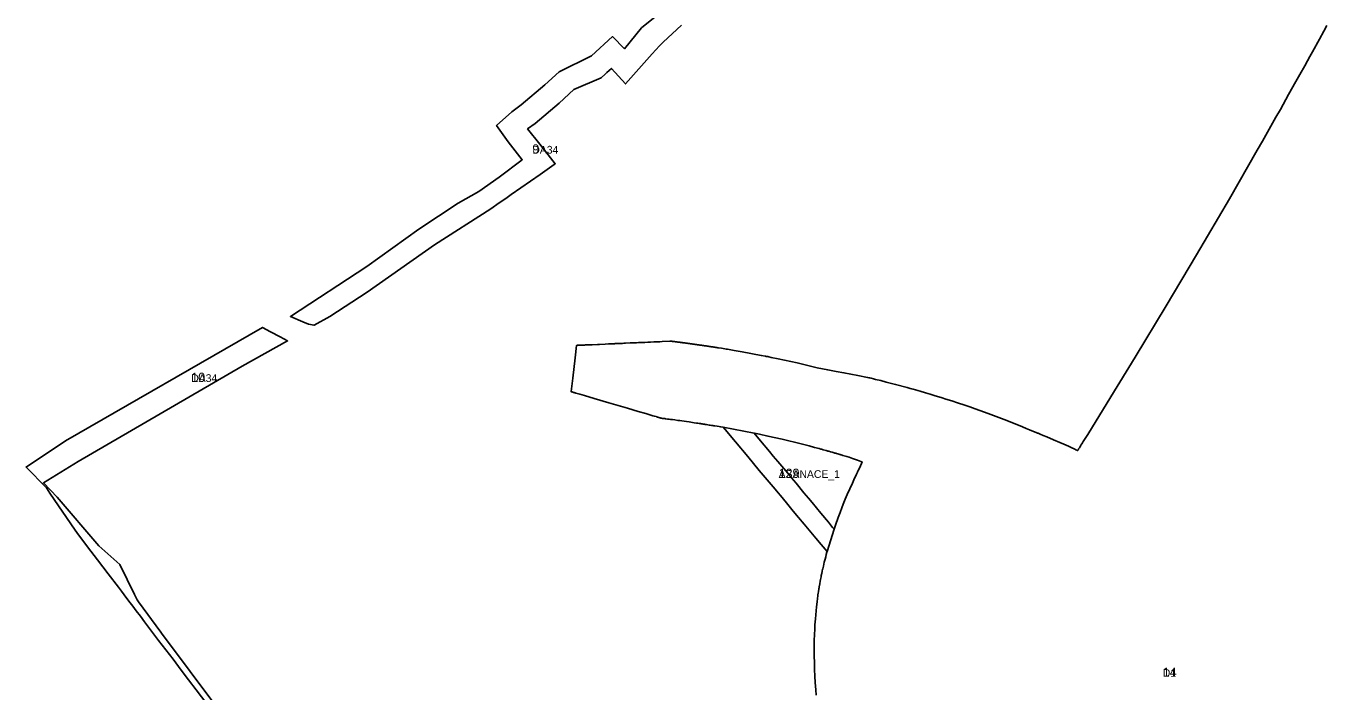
# Model space of a CAD drawing. Extents: x -537012 to -534603, y -1176562 to -1172739.
# Drawn here: x -536960 to -536122, y -1174561 to -1174132 of the extents above; entities that cross this region are included whole.
import ezdxf

# ---------------------------------------------------------------- set-up
doc = ezdxf.new("R2010")
doc.units = 0
for name, color, linetype in [('96070023', 7, 'Continuous'), ('96120023', 7, 'Continuous'), ('96140023', 7, 'Continuous'), ('ID_A', 7, 'Continuous'), ('ID_VPO', 7, 'Continuous'), ('ID_VPS', 7, 'Continuous')]:
    doc.layers.add(name, color=color, linetype=linetype)

msp = doc.modelspace()

# ---------------------------------------------------------------- linework, layer by layer
at = {"layer": '96070023'}
msp.add_lwpolyline([(-536510.97, -1174390.13), (-536491.16, -1174393.88), (-536487.08, -1174398.75), (-536481.33, -1174405.62), (-536478.81, -1174408.63), (-536475.89, -1174412.11), (-536469.54, -1174419.69), (-536467.05, -1174422.67), (-536464.18, -1174426.13), (-536459.11, -1174432.25), (-536456.15, -1174435.81), (-536453.87, -1174438.55), (-536448.28, -1174445.29), (-536443.37, -1174451.21), (-536440.62, -1174454.52), (-536439.72, -1174455.61), (-536444.22, -1174470.15), (-536448.09, -1174465.49), (-536451.43, -1174461.48), (-536458.89, -1174452.51), (-536462.53, -1174448.14), (-536465.96, -1174444.02), (-536469.4, -1174439.87), (-536473.17, -1174435.33), (-536476.74, -1174431.03), (-536477.7, -1174429.89), (-536481.51, -1174425.34), (-536487.81, -1174417.82), (-536495.28, -1174408.89), (-536503.16, -1174399.47), (-536509.84, -1174391.48)], close=True, dxfattribs=at)
at = {"layer": '96120023'}
msp.add_lwpolyline([(-536451.2, -1174562.49), (-536451.47, -1174559.05), (-536451.8, -1174554.37), (-536452.04, -1174550.3), (-536452.23, -1174546.1), (-536452.35, -1174542.66), (-536452.48, -1174536.44), (-536452.5, -1174532.78), (-536452.43, -1174527.15), (-536452.33, -1174523.79), (-536452.16, -1174519.88), (-536452.02, -1174517.4), (-536451.75, -1174513.36), (-536451.53, -1174510.81), (-536451.29, -1174508.22), (-536451.02, -1174505.61), (-536450.65, -1174502.44), (-536450.38, -1174500.38), (-536450.16, -1174498.73), (-536450.06, -1174498.03), (-536449.9, -1174496.98), (-536449.75, -1174495.96), (-536449.63, -1174495.19), (-536449.58, -1174494.88), (-536449.54, -1174494.59), (-536449.48, -1174494.26), (-536449.44, -1174493.97), (-536449.4, -1174493.77), (-536449.38, -1174493.66), (-536449.37, -1174493.59), (-536449.36, -1174493.51), (-536449.35, -1174493.46), (-536449.35, -1174493.45), (-536449.34, -1174493.41), (-536449.34, -1174493.4), (-536449.34, -1174493.39), (-536449.34, -1174493.38), (-536449.34, -1174493.37), (-536449.33, -1174493.36), (-536449.33, -1174493.35), (-536449.33, -1174493.34), (-536449.32, -1174493.29), (-536449.32, -1174493.28), (-536449.32, -1174493.25), (-536449.31, -1174493.22), (-536449.3, -1174493.17), (-536449.3, -1174493.16), (-536449.3, -1174493.15), (-536449.3, -1174493.13), (-536449.29, -1174493.12), (-536449.29, -1174493.11), (-536449.29, -1174493.1), (-536449.29, -1174493.09), (-536449.29, -1174493.07), (-536449.28, -1174493.06), (-536449.27, -1174492.95), (-536449.26, -1174492.94), (-536449.26, -1174492.93), (-536449.26, -1174492.91), (-536449.25, -1174492.87), (-536449.25, -1174492.83), (-536448.92, -1174490.92), (-536448.6, -1174489.21), (-536448.4, -1174488.1), (-536448.06, -1174486.4), (-536447.9, -1174485.53), (-536447.78, -1174484.97), (-536447.76, -1174484.86), (-536447.74, -1174484.78), (-536447.74, -1174484.77), (-536447.73, -1174484.75), (-536447.73, -1174484.74), (-536447.73, -1174484.73), (-536447.72, -1174484.7), (-536447.71, -1174484.65), (-536447.7, -1174484.59), (-536447.68, -1174484.5), (-536447.66, -1174484.39), (-536447.65, -1174484.33), (-536447.63, -1174484.24), (-536447.62, -1174484.19), (-536447.6, -1174484.11), (-536447.59, -1174484.05), (-536447.57, -1174483.97), (-536447.56, -1174483.92), (-536447.54, -1174483.83), (-536447.53, -1174483.76), (-536447.5, -1174483.64), (-536447.48, -1174483.54), (-536447.44, -1174483.34), (-536447.27, -1174482.55), (-536447.06, -1174481.6), (-536446.96, -1174481.14), (-536446.6, -1174479.57), (-536445.99, -1174476.98), (-536445.48, -1174474.94), (-536445.09, -1174473.42), (-536444.7, -1174471.91), (-536444.29, -1174470.42), (-536444.22, -1174470.15), (-536439.72, -1174455.61), (-536438.86, -1174453.07), (-536437.13, -1174448.29), (-536435.86, -1174444.91), (-536434.73, -1174442.03), (-536433.76, -1174439.61), (-536432.46, -1174436.46), (-536431.16, -1174433.39), (-536429.52, -1174429.63), (-536427.91, -1174426.04), (-536426.96, -1174423.95), (-536425.23, -1174420.22), (-536425.08, -1174419.89), (-536424.92, -1174419.56), (-536424.77, -1174419.23), (-536424.61, -1174418.91), (-536424.3, -1174418.25), (-536424.15, -1174417.93), (-536423.84, -1174417.28), (-536423.54, -1174416.64), (-536423.39, -1174416.33), (-536423.08, -1174415.69), (-536422.78, -1174415.06), (-536422.63, -1174414.75), (-536422.33, -1174414.13), (-536422.03, -1174413.51), (-536421.74, -1174412.9), (-536421.59, -1174412.6), (-536421.54, -1174412.48), (-536422.54, -1174412.11), (-536424.58, -1174411.36), (-536425.85, -1174410.9), (-536427.9, -1174410.15), (-536428.97, -1174409.76), (-536430, -1174409.39), (-536431.52, -1174408.9), (-536433.26, -1174408.41), (-536434.09, -1174408.16), (-536434.45, -1174408.05), (-536434.73, -1174407.97), (-536434.95, -1174407.91), (-536435.07, -1174407.87), (-536435.18, -1174407.84), (-536435.31, -1174407.8), (-536435.36, -1174407.79), (-536435.45, -1174407.76), (-536435.54, -1174407.73), (-536435.61, -1174407.71), (-536435.71, -1174407.68), (-536435.85, -1174407.64), (-536436, -1174407.6), (-536436.14, -1174407.55), (-536436.35, -1174407.49), (-536436.52, -1174407.44), (-536436.73, -1174407.38), (-536436.91, -1174407.33), (-536437.07, -1174407.28), (-536437.23, -1174407.24), (-536437.37, -1174407.2), (-536438.08, -1174406.99), (-536438.63, -1174406.83), (-536439.11, -1174406.69), (-536439.6, -1174406.55), (-536440.93, -1174406.17), (-536441.94, -1174405.88), (-536443.08, -1174405.56), (-536443.61, -1174405.41), (-536444.04, -1174405.29), (-536444.75, -1174405.09), (-536446.75, -1174404.53), (-536447.13, -1174404.43), (-536447.86, -1174404.23), (-536448.31, -1174404.11), (-536449.26, -1174403.84), (-536452.2, -1174403.06), (-536455.68, -1174402.13), (-536460.81, -1174400.81), (-536473.13, -1174397.82), (-536482.28, -1174395.75), (-536487.7, -1174394.6), (-536490.84, -1174393.94), (-536491.16, -1174393.88), (-536510.97, -1174390.13), (-536512.58, -1174389.85), (-536513.65, -1174389.66), (-536514.86, -1174389.46), (-536516.34, -1174389.22), (-536517.14, -1174389.09), (-536517.72, -1174389), (-536518.57, -1174388.86), (-536519.43, -1174388.72), (-536520, -1174388.63), (-536520.86, -1174388.49), (-536521.72, -1174388.36), (-536522.58, -1174388.22), (-536523.16, -1174388.13), (-536524.02, -1174388), (-536524.59, -1174387.91), (-536525.17, -1174387.82), (-536525.74, -1174387.74), (-536526.6, -1174387.61), (-536527.47, -1174387.48), (-536528.33, -1174387.35), (-536529.78, -1174387.14), (-536531.8, -1174386.84), (-536532.95, -1174386.67), (-536534.69, -1174386.43), (-536536.14, -1174386.22), (-536537.59, -1174386.02), (-536539.04, -1174385.82), (-536540.21, -1174385.66), (-536542.24, -1174385.39), (-536543.7, -1174385.19), (-536544.87, -1174385.04), (-536545.75, -1174384.92), (-536546.91, -1174384.77), (-536548.08, -1174384.62), (-536548.67, -1174384.54), (-536549.25, -1174384.47), (-536550.13, -1174384.35), (-536550.72, -1174384.28), (-536550.8, -1174384.27), (-536551.11, -1174384.18), (-536551.25, -1174384.14), (-536551.52, -1174384.05), (-536551.73, -1174384), (-536551.88, -1174383.95), (-536552.01, -1174383.91), (-536552.16, -1174383.87), (-536552.32, -1174383.82), (-536552.47, -1174383.78), (-536552.7, -1174383.71), (-536552.9, -1174383.65), (-536553.08, -1174383.6), (-536553.13, -1174383.58), (-536553.17, -1174383.57), (-536553.2, -1174383.56), (-536553.31, -1174383.53), (-536553.32, -1174383.53), (-536553.33, -1174383.52), (-536553.35, -1174383.52), (-536553.38, -1174383.51), (-536553.42, -1174383.5), (-536553.44, -1174383.49), (-536553.47, -1174383.48), (-536553.58, -1174383.45), (-536553.69, -1174383.42), (-536553.93, -1174383.35), (-536554.26, -1174383.25), (-536555.38, -1174382.92), (-536556.34, -1174382.65), (-536560.82, -1174381.31), (-536565.68, -1174379.89), (-536572.72, -1174377.81), (-536577.15, -1174376.5), (-536584.69, -1174374.31), (-536594, -1174371.48), (-536600.21, -1174369.7), (-536603.24, -1174368.81), (-536605.96, -1174368.03), (-536606.38, -1174367.91), (-536606.6, -1174367.84), (-536606.91, -1174367.75), (-536607.13, -1174367.69), (-536607.41, -1174367.61), (-536607.79, -1174367.49), (-536607.91, -1174367.46), (-536608.28, -1174367.35), (-536608.57, -1174367.26), (-536608.67, -1174367.23), (-536608.72, -1174367.22), (-536608.75, -1174367.21), (-536608.77, -1174367.2), (-536608.79, -1174367.2), (-536608.8, -1174367.19), (-536608.84, -1174367.18), (-536608.87, -1174367.17), (-536608.9, -1174367.16), (-536608.94, -1174367.15), (-536608.95, -1174367.15), (-536608.97, -1174367.14), (-536608.98, -1174367.14), (-536607.93, -1174358.38), (-536606.37, -1174345.41), (-536605.4, -1174337.35), (-536605.12, -1174337.34), (-536604.97, -1174337.33), (-536604.91, -1174337.33), (-536604.85, -1174337.33), (-536604.82, -1174337.33), (-536604.79, -1174337.33), (-536604.77, -1174337.33), (-536604.73, -1174337.32), (-536604.58, -1174337.32), (-536604.4, -1174337.31), (-536603.84, -1174337.28), (-536603.53, -1174337.27), (-536603.07, -1174337.25), (-536602.54, -1174337.23), (-536601.36, -1174337.17), (-536600.24, -1174337.12), (-536599.58, -1174337.1), (-536598.23, -1174337.04), (-536597.56, -1174337.01), (-536596.59, -1174336.97), (-536595.37, -1174336.92), (-536591.92, -1174336.76), (-536590.61, -1174336.7), (-536586.99, -1174336.54), (-536584.83, -1174336.45), (-536583.28, -1174336.38), (-536582.56, -1174336.34), (-536581.61, -1174336.3), (-536581.02, -1174336.28), (-536580.57, -1174336.26), (-536579.54, -1174336.21), (-536579.2, -1174336.2), (-536578.84, -1174336.18), (-536578.38, -1174336.16), (-536575.77, -1174336.05), (-536574.97, -1174336.01), (-536573.85, -1174335.96), (-536570.88, -1174335.83), (-536569.64, -1174335.78), (-536566.9, -1174335.65), (-536565.46, -1174335.59), (-536564.48, -1174335.55), (-536564.02, -1174335.53), (-536563.49, -1174335.51), (-536562.91, -1174335.48), (-536562.13, -1174335.45), (-536561.89, -1174335.44), (-536561.73, -1174335.43), (-536561.56, -1174335.42), (-536559.51, -1174335.33), (-536557.75, -1174335.25), (-536555.74, -1174335.17), (-536554.25, -1174335.1), (-536553.77, -1174335.08), (-536552.29, -1174335.01), (-536551.83, -1174334.99), (-536550.25, -1174334.92), (-536545.34, -1174334.71), (-536545.23, -1174334.7), (-536545.07, -1174334.69), (-536544.97, -1174334.69), (-536544.89, -1174334.69), (-536544.83, -1174334.68), (-536544.78, -1174334.68), (-536544.73, -1174334.68), (-536544.72, -1174334.68), (-536544.71, -1174334.68), (-536544.7, -1174334.68), (-536544.69, -1174334.68), (-536544.68, -1174334.68), (-536544.67, -1174334.68), (-536544.66, -1174334.68), (-536544.66, -1174334.67), (-536544.65, -1174334.67), (-536544.64, -1174334.67), (-536544.63, -1174334.67), (-536544.61, -1174334.67), (-536544.6, -1174334.67), (-536544.59, -1174334.67), (-536544.58, -1174334.67), (-536544.55, -1174334.67), (-536544.54, -1174334.67), (-536544.53, -1174334.67), (-536544.52, -1174334.67), (-536544.51, -1174334.67), (-536544.5, -1174334.67), (-536544.49, -1174334.67), (-536544.48, -1174334.67), (-536544.47, -1174334.67), (-536544.46, -1174334.67), (-536544.45, -1174334.67), (-536544.44, -1174334.68), (-536544.43, -1174334.68), (-536544.42, -1174334.68), (-536544.38, -1174334.68), (-536544.08, -1174334.72), (-536543.78, -1174334.76), (-536543.47, -1174334.8), (-536543.17, -1174334.84), (-536542.87, -1174334.88), (-536542.57, -1174334.92), (-536542.27, -1174334.95), (-536541.96, -1174334.99), (-536541.66, -1174335.03), (-536541.36, -1174335.07), (-536541.06, -1174335.11), (-536540.75, -1174335.15), (-536540.45, -1174335.19), (-536540.15, -1174335.23), (-536539.85, -1174335.27), (-536539.54, -1174335.31), (-536539.24, -1174335.35), (-536538.94, -1174335.39), (-536538.63, -1174335.43), (-536538.33, -1174335.47), (-536538.03, -1174335.51), (-536537.73, -1174335.55), (-536537.42, -1174335.59), (-536537.12, -1174335.63), (-536536.82, -1174335.67), (-536536.51, -1174335.71), (-536536.21, -1174335.75), (-536535.91, -1174335.79), (-536535.6, -1174335.83), (-536535.3, -1174335.87), (-536535, -1174335.91), (-536534.69, -1174335.95), (-536534.39, -1174335.99), (-536534.09, -1174336.04), (-536533.78, -1174336.08), (-536533.48, -1174336.12), (-536533.18, -1174336.16), (-536532.87, -1174336.2), (-536532.57, -1174336.24), (-536532.26, -1174336.28), (-536531.96, -1174336.33), (-536531.66, -1174336.37), (-536531.35, -1174336.41), (-536531.05, -1174336.45), (-536530.75, -1174336.49), (-536530.44, -1174336.54), (-536530.14, -1174336.58), (-536529.83, -1174336.62), (-536529.53, -1174336.66), (-536529.22, -1174336.7), (-536528.92, -1174336.75), (-536528.62, -1174336.79), (-536528.31, -1174336.83), (-536528.01, -1174336.88), (-536527.7, -1174336.92), (-536527.4, -1174336.96), (-536527.09, -1174337), (-536526.79, -1174337.05), (-536526.18, -1174337.13), (-536525.57, -1174337.22), (-536524.96, -1174337.31), (-536524.35, -1174337.4), (-536523.74, -1174337.49), (-536523.13, -1174337.57), (-536522.52, -1174337.66), (-536521.91, -1174337.75), (-536521.3, -1174337.84), (-536520.69, -1174337.93), (-536520.08, -1174338.03), (-536519.47, -1174338.12), (-536518.86, -1174338.21), (-536518.25, -1174338.3), (-536517.64, -1174338.4), (-536517.03, -1174338.49), (-536516.41, -1174338.58), (-536515.8, -1174338.68), (-536515.19, -1174338.77), (-536514.58, -1174338.87), (-536513.97, -1174338.96), (-536512.13, -1174339.25), (-536509.98, -1174339.6), (-536509.07, -1174339.75), (-536509.06, -1174339.75), (-536509.05, -1174339.75), (-536509.04, -1174339.75), (-536509.03, -1174339.76), (-536509.01, -1174339.76), (-536508.97, -1174339.77), (-536508.8, -1174339.79), (-536508.25, -1174339.88), (-536504.04, -1174340.59), (-536498.74, -1174341.52), (-536486.52, -1174343.8), (-536483.81, -1174344.35), (-536483.35, -1174344.44), (-536482.72, -1174344.57), (-536482.41, -1174344.63), (-536481.74, -1174344.77), (-536480.22, -1174345.08), (-536475.59, -1174346.07), (-536463.41, -1174348.62), (-536450.5, -1174351.85), (-536443.72, -1174353.14), (-536438.38, -1174354.08), (-536433.4, -1174354.97), (-536424.41, -1174356.74), (-536418.11, -1174358.01), (-536417.29, -1174358.2), (-536416.64, -1174358.36), (-536415.89, -1174358.54), (-536414.22, -1174358.94), (-536412.92, -1174359.26), (-536409.68, -1174360.06), (-536406.21, -1174360.95), (-536400.1, -1174362.55), (-536392.72, -1174364.52), (-536390.66, -1174365.1), (-536389.74, -1174365.36), (-536388.73, -1174365.64), (-536384.28, -1174366.93), (-536380.84, -1174367.93), (-536377.82, -1174368.83), (-536374.68, -1174369.78), (-536372.29, -1174370.52), (-536370.22, -1174371.18), (-536367.71, -1174371.96), (-536363.95, -1174373.15), (-536360.21, -1174374.36), (-536355.46, -1174375.92), (-536352.24, -1174377.01), (-536348.81, -1174378.18), (-536342.81, -1174380.27), (-536338.75, -1174381.78), (-536328.56, -1174385.71), (-536318.46, -1174389.9), (-536316.07, -1174390.85), (-536313.99, -1174391.68), (-536312.38, -1174392.33), (-536310.75, -1174392.99), (-536310.21, -1174393.21), (-536309.68, -1174393.43), (-536308.82, -1174393.78), (-536308.4, -1174393.96), (-536308, -1174394.12), (-536307.46, -1174394.35), (-536307.03, -1174394.52), (-536305.03, -1174395.35), (-536302.76, -1174396.3), (-536298.38, -1174398.15), (-536294.29, -1174399.94), (-536291.82, -1174401.02), (-536288.89, -1174402.34), (-536287.03, -1174403.18), (-536284.74, -1174404.22), (-536283.99, -1174404.56), (-536283.5, -1174404.79), (-536282.92, -1174405.06), (-536282.92, -1174405.05), (-536282.91, -1174405.05), (-536282.91, -1174405.04), (-536282.88, -1174404.99), (-536282.83, -1174404.91), (-536282.8, -1174404.87), (-536282.79, -1174404.85), (-536282.78, -1174404.84), (-536282.77, -1174404.82), (-536282.76, -1174404.8), (-536282.64, -1174404.62), (-536282.44, -1174404.3), (-536282.28, -1174404.03), (-536282, -1174403.59), (-536281.78, -1174403.24), (-536281.6, -1174402.95), (-536281.38, -1174402.6), (-536281.05, -1174402.07), (-536280.79, -1174401.65), (-536280.27, -1174400.82), (-536279.8, -1174400.06), (-536279.32, -1174399.29), (-536278.12, -1174397.41), (-536276.47, -1174394.75), (-536261.5, -1174370.57), (-536245.85, -1174344.89), (-536226.04, -1174311.88), (-536206.47, -1174279.11), (-536185.2, -1174242.92), (-536167.39, -1174211.76), (-536164.05, -1174205.81), (-536155.4, -1174190.41), (-536152.46, -1174185.52), (-536147.2, -1174175.86), (-536142.44, -1174167.42), (-536139.87, -1174162.9), (-536136.81, -1174157.4), (-536134.98, -1174154.09), (-536133.51, -1174151.34), (-536131.8, -1174148.29), (-536127.34, -1174140.28), (-536124.46, -1174135.08), (-536122.45, -1174131.35)], dxfattribs=at)
at = {"layer": '96140023'}
for points in [[(-536537.99, -1174131.12), (-536549.77, -1174142.2), (-536552.09, -1174144.39), (-536556.68, -1174149.57), (-536573.89, -1174168.98), (-536582.98, -1174159), (-536585.99, -1174161.74), (-536586.97, -1174162.65), (-536589.69, -1174165.16), (-536607.24, -1174172.71), (-536616.56, -1174181.4), (-536632.01, -1174194.48), (-536636.91, -1174197.98), (-536629.05, -1174207.9), (-536619.11, -1174220.46), (-536621.41, -1174222.06), (-536628.95, -1174227.33), (-536647.48, -1174240.27), (-536650.9, -1174242.7), (-536655.21, -1174245.53), (-536660.63, -1174249.48), (-536696.77, -1174272.73), (-536740.11, -1174303.11), (-536764.27, -1174318.86), (-536774.32, -1174324.36), (-536777.86, -1174323.74), (-536781.56, -1174322.19), (-536789.62, -1174318.82), (-536740.36, -1174286.49), (-536706.97, -1174262.51), (-536681.6, -1174245.85), (-536668.42, -1174238.35), (-536655.27, -1174229.14), (-536640.42, -1174217.81), (-536649.38, -1174206.4), (-536656.94, -1174195.79), (-536647.14, -1174187.01), (-536641.13, -1174182.57), (-536625.9, -1174169.67), (-536616.62, -1174161.14), (-536595.84, -1174150.89), (-536582.3, -1174138.54), (-536574.58, -1174146.41), (-536563.66, -1174133), (-536547.35, -1174119.82)], [(-536843.46, -1174568.06), (-536850.22, -1174559.15), (-536855.16, -1174552.64), (-536859.89, -1174546.41), (-536865.14, -1174539.49), (-536869.7, -1174533.48), (-536874.4, -1174527.28), (-536883.47, -1174515.33), (-536886.13, -1174511.82), (-536888.89, -1174508.18), (-536891.02, -1174505.37), (-536893.56, -1174502.02), (-536896.58, -1174498.04), (-536898.39, -1174495.66), (-536900.32, -1174493.11), (-536906.91, -1174484.44), (-536913.8, -1174475.36), (-536920.15, -1174466.99), (-536927.13, -1174457.78), (-536928.15, -1174456.44), (-536944.35, -1174432.42), (-536946.53, -1174429.18), (-536959.76, -1174415.72), (-536934.44, -1174398.77), (-536807.66, -1174325.78), (-536802.4, -1174328.6), (-536796.2, -1174331.92), (-536791.46, -1174334.47), (-536820.61, -1174350.66), (-536926.13, -1174412.06), (-536948.53, -1174425.88), (-536939.8, -1174435.07), (-536912.85, -1174466.49), (-536899.48, -1174478.39), (-536890.01, -1174497.84), (-536888.12, -1174501.1), (-536887.36, -1174502.41), (-536873.06, -1174521.97), (-536872.53, -1174522.68), (-536835.56, -1174572.01)]]:
    msp.add_lwpolyline(points, dxfattribs=at)

# ---------------------------------------------------------------- texts
at = {"layer": '96070023'}
msp.add_text('ASANACE_1', height=5, rotation=0, dxfattribs=at).set_placement((-536475.35, -1174422.74))
at = {"layer": '96120023'}
msp.add_text('D1', height=5, rotation=0, dxfattribs=at).set_placement((-536228.11, -1174550.77))
at = {"layer": '96140023'}
for p in [(-536633.89, -1174213.91), (-536853.42, -1174360.94)]:
    msp.add_text('DA34', height=5, rotation=0, dxfattribs=at).set_placement(p)
at = {"layer": 'ID_A'}
msp.add_text('129', height=6, rotation=0, dxfattribs=at).set_placement((-536475.35, -1174422.74))
at = {"layer": 'ID_VPO'}
for s, p in [('9', (-536633.89, -1174213.91)), ('10', (-536853.42, -1174360.94))]:
    msp.add_text(s, height=6, rotation=0, dxfattribs=at).set_placement(p)
at = {"layer": 'ID_VPS'}
msp.add_text('14', height=6, rotation=360, dxfattribs=at).set_placement((-536228.11, -1174550.77))

doc.saveas('drawing.dxf')
